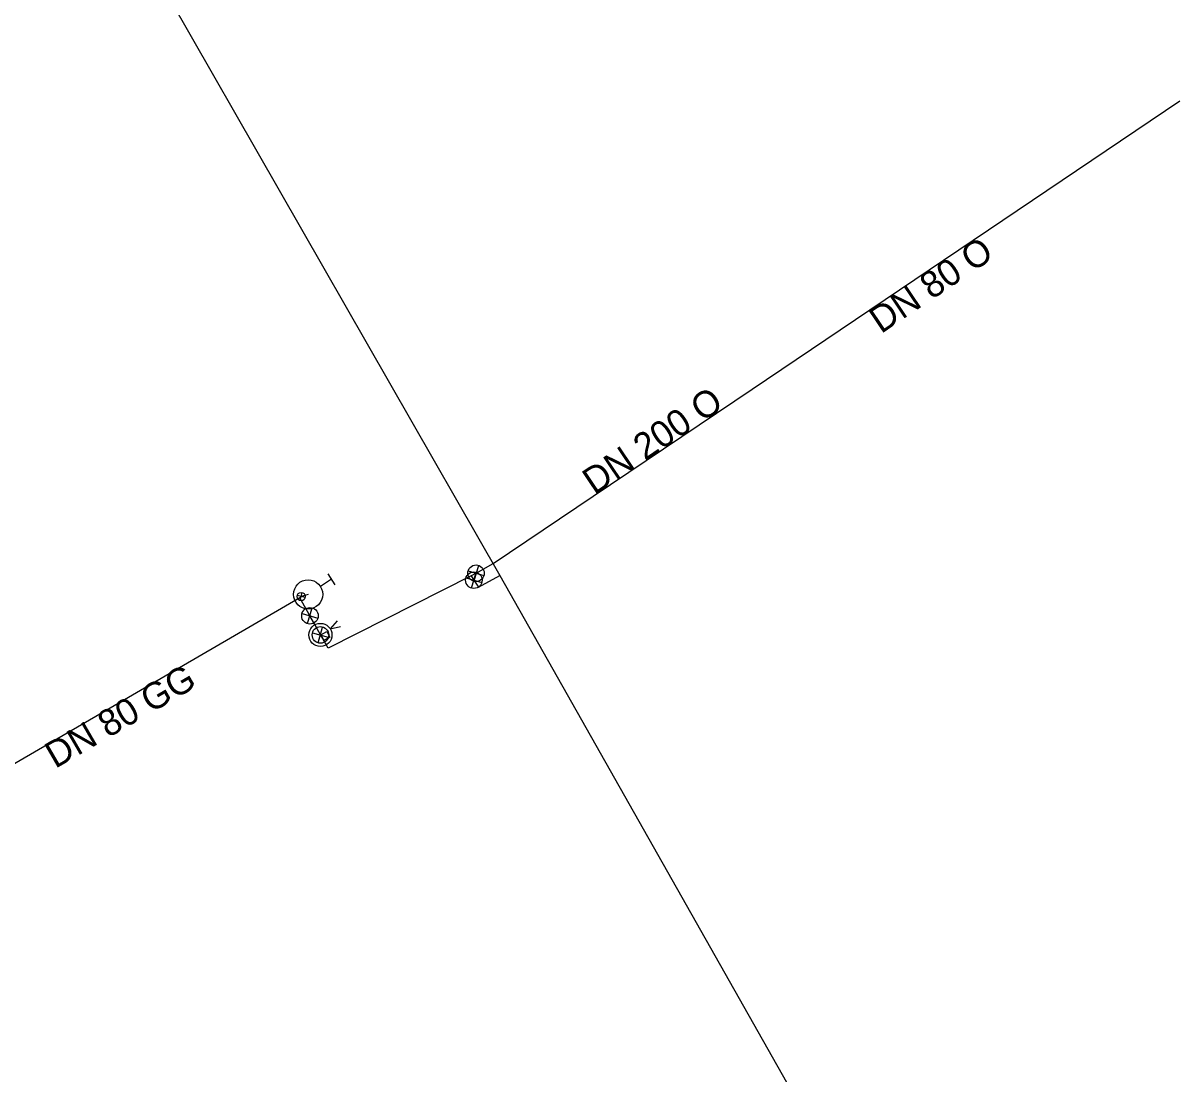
# Model space of a CAD drawing. Extents: x -443562 to -443270, y -1122830 to -1122511.
# Drawn here: x -443339.8 to -443269.8, y -1122738.8 to -1122675.2 of the extents above; entities that cross this region are included whole.
import ezdxf

# ---------------------------------------------------------------- set-up
doc = ezdxf.new("R2010")
doc.units = 0
for name, color, linetype in [('_hydrantova_odbocka_', 7, 'Continuous'), ('_voda_smvak_prevzato_z_dokumentace_', 7, 'Continuous'), ('_vodovodni_chranicka_', 7, 'Continuous'), ('Default', 7, 'Continuous'), ('MoLevel 27', 7, 'Continuous'), ('MoLevel 28', 7, 'Continuous'), ('MoLevel 30', 7, 'Continuous'), ('MoLevel 42', 7, 'Continuous'), ('MoLevel 46', 7, 'Continuous'), ('MoLevel 60', 7, 'Continuous')]:
    doc.layers.add(name, color=color, linetype=linetype)

# ---------------------------------------------------------------- blocks, each defined once
blk = doc.blocks.new('_uzaver_')
at = {"layer": 'Default'}
for p, q in [((-0.000035, -0.000035), (0.000035, 0.000035)), ((0.000035, -0.000035), (-0.000035, 0.000035))]:
    blk.add_line(p, q, dxfattribs=at)
for radius in [0.00005, 0.0000025]:
    blk.add_circle((0, 0), radius, dxfattribs=at)
blk = doc.blocks.new('_hydrant_voda_')
at = {"layer": 'Default'}
for p, q in [((-0.0000225, 0.000095), (0.0000225, 0.000095)), ((0, 0.000095), (0, 0.00005))]:
    blk.add_line(p, q, dxfattribs=at)
blk.add_circle((0, 0), 0.00005, dxfattribs=at)
blk = doc.blocks.new('_sachta_voda_')
at = {"layer": 'Default'}
blk.add_lwpolyline([(-0.00001, 0.000065), (0, 0.000035), (0.00001, 0.000065)], dxfattribs=at)
blk.add_circle((0, 0), 0.000035, dxfattribs=at)
blk = doc.blocks.new('_poklop_voda_')
at = {"layer": 'Default'}
blk.add_lwpolyline([(-0.00002, 0.00002), (0.00002, 0.00002), (0.00002, -0.00002), (-0.00002, -0.00002), (-0.00002, 0.00002)], dxfattribs=at)

msp = doc.modelspace()

# ---------------------------------------------------------------- linework, layer by layer
at = {"layer": '_hydrantova_odbocka_'}
msp.add_lwpolyline([(-443322.58, -1122709.79), (-443323, -1122709.92), (-443323.09, -1122710)], dxfattribs=at)
at = {"layer": '_voda_smvak_prevzato_z_dokumentace_'}
for p, q in [((-443376.68, -1122593.89), (-443310.987, -1122708.637)), ((-443295.706, -1122697.36), (-443269.826, -1122679.921)), ((-443305.334, -1122703.848), (-443295.706, -1122697.36)), ((-443312.42, -1122708.51), (-443312.707, -1122708.664)), ((-443312.707, -1122708.664), (-443312.55, -1122708.93)), ((-443310.987, -1122708.637), (-443269.826, -1122781.333)), ((-443322.611, -1122710.831), (-443323.09, -1122710)), ((-443322.471, -1122711.085), (-443322.611, -1122710.831)), ((-443322.261, -1122711.467), (-443322.471, -1122711.085)), ((-443321.835, -1122712.242), (-443322.261, -1122711.467)), ((-443321.531, -1122712.761), (-443321.835, -1122712.242))]:
    msp.add_line(p, q, dxfattribs=at)
for points in [[(-443312.42, -1122708.51), (-443311.391, -1122707.93), (-443305.334, -1122703.848)], [(-443312.707, -1122708.664), (-443321.368, -1122713.037), (-443321.531, -1122712.761)], [(-443312.55, -1122708.93), (-443312.268, -1122709.352), (-443310.987, -1122708.637)], [(-443323.09, -1122710), (-443346.19, -1122723.44), (-443346.631, -1122723.693)]]:
    msp.add_lwpolyline(points, dxfattribs=at)
at = {"layer": '_vodovodni_chranicka_'}
msp.add_line((-443305.334, -1122703.848), (-443295.706, -1122697.36), dxfattribs=at)

# ---------------------------------------------------------------- block references
at = {"layer": 'MoLevel 27'}
for p, xscale, yscale, rotation in [((-443312.55, -1122708.93), 10000.000000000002, 10000.000000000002, -61.51785555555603), ((-443312.42, -1122708.51), 10000, 10000, -151.62226339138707), ((-443323, -1122709.92), 5000, 4999.999999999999, 31.3570861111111), ((-443322.471, -1122711.085), 10000, 9999.999999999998, -61.18388597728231), ((-443321.835, -1122712.242), 10000, 10000, -60.29837500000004)]:
    msp.add_blockref('_uzaver_', p, dxfattribs=dict(at, xscale=xscale, yscale=yscale, rotation=rotation))
at = {"layer": 'MoLevel 28', "xscale": 17636.68430335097, "yscale": 17636.684303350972, "rotation": -56.968066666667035}
msp.add_blockref('_hydrant_voda_', (-443322.58, -1122709.79), dxfattribs=at)
at = {"layer": 'MoLevel 30', "xscale": 20000, "yscale": 19999.999999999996, "rotation": -58.53742222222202}
msp.add_blockref('_sachta_voda_', (-443321.836, -1122712.242), dxfattribs=at)
at = {"layer": 'MoLevel 42', "xscale": 10000.000000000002, "yscale": 9999.999999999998, "rotation": -60.46015912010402}
msp.add_blockref('_poklop_voda_', (-443321.53, -1122712.31), dxfattribs=at)

# ---------------------------------------------------------------- texts
at = {"layer": 'MoLevel 46'}
for s, rotation, p in [('DN 80 O', 33.97458, (-443287.915, -1122694.046)), ('DN 80 GG', 30.19163, (-443337.883, -1122720.358))]:
    msp.add_text(s, height=1.6049, rotation=rotation, dxfattribs=at).set_placement(p)
at = {"layer": 'MoLevel 60'}
msp.add_text('DN 200 O', height=1.6049, rotation=33.97427, dxfattribs=at).set_placement((-443305.261, -1122703.799))

doc.saveas('drawing.dxf')
